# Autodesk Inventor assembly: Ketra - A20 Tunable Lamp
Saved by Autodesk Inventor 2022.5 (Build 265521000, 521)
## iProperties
Created: 2024-07
Part Number: Ketra - A20 Tunable Lamp
Document SubType Name: Assembly
Designer: AdminForWorker
Title: Ketra - A20 Tunable Lamp v4
Author: AdminForWorker
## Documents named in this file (2)
- z:\worker\convert-fusion-r03-cosv3\tmp\job-1\32\temp\files\f0bacd61-cbe3-4501-ac2f-e71adfe0b3b0\Ketra - A20 Tunable Lamp v4.iam
- z:\worker\convert-fusion-r03-cosv3\tmp\job-1\32\temp\files\f0bacd61-cbe3-4501-ac2f-e71adfe0b3b0\Ketra A20.ipt
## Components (1 placed, 1 different names)
1. Ketra A20:1
